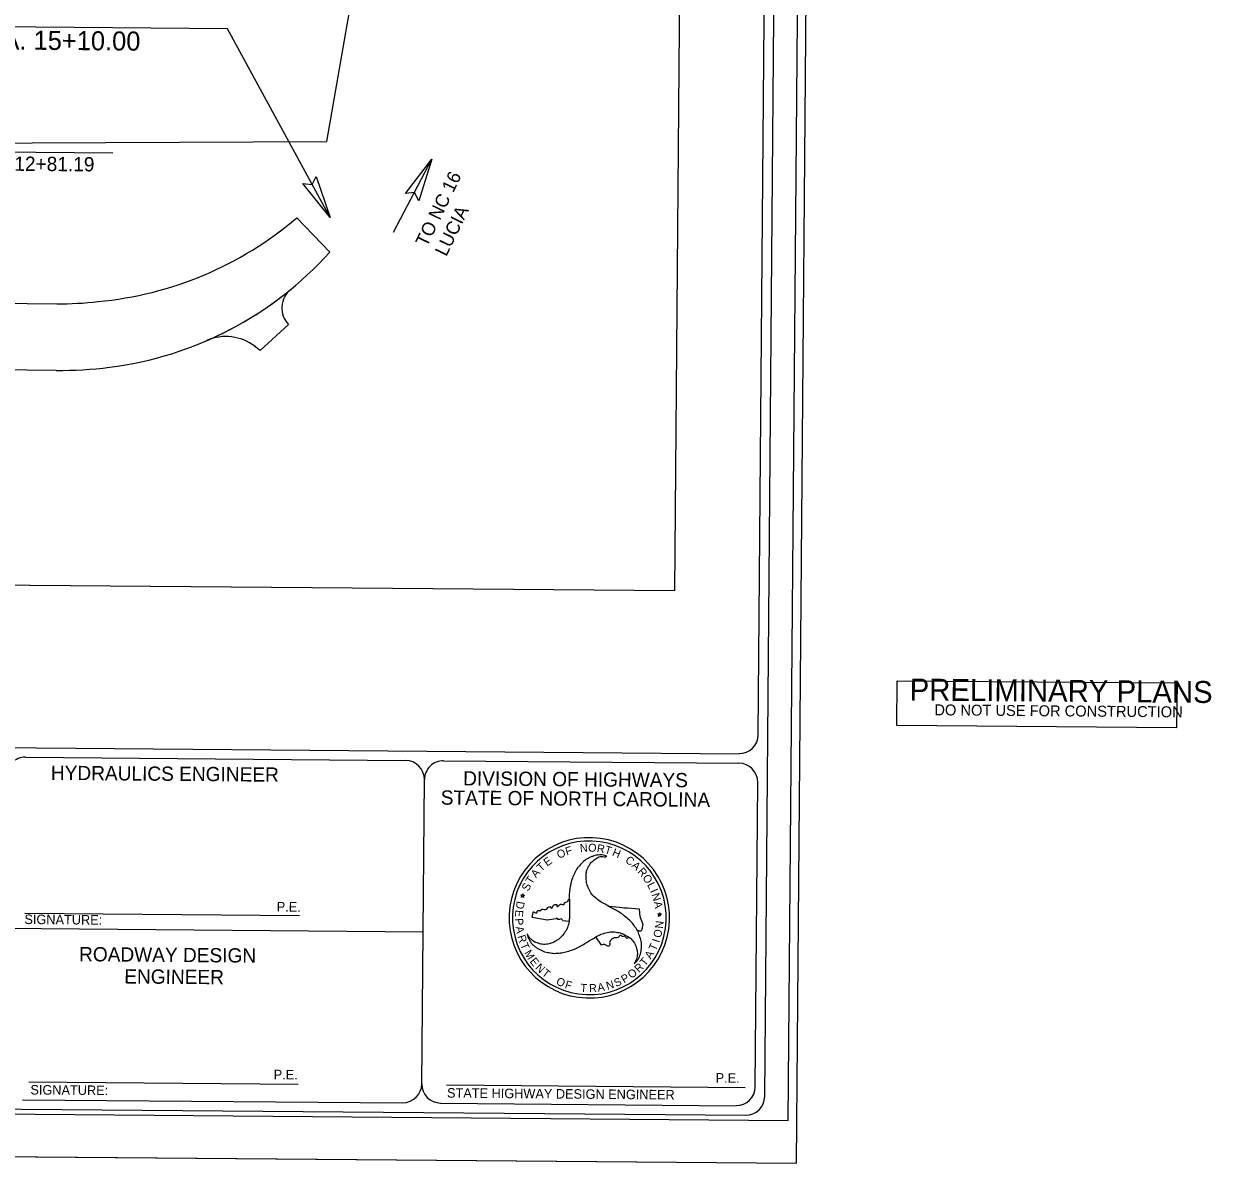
# Model space of a CAD drawing. Extents: x 1379453 to 1387082, y 594364 to 596664.
# Drawn here: x 1382008 to 1383256, y 594364 to 595562 of the extents above; entities that cross this region are included whole.
import ezdxf

# ---------------------------------------------------------------- set-up
doc = ezdxf.new("R2010")
doc.units = 0
for name, color, linetype in [('Old_Level_32', 7, 'Continuous'), ('Prop Horizontal Alignment Station Label', 7, 'Continuous'), ('Prop Shade Medium', 7, 'Continuous'), ('Prop Terminator CELL', 7, 'Continuous'), ('Sheet Clip Boundary CELL', 7, 'Continuous'), ('Sheet Cutting Line CELL', 7, 'Continuous'), ('Sheet Plot Border Inside CELL', 7, 'Continuous'), ('Sheet Plot Border Outside CELL', 7, 'Continuous'), ('Sheet Sticker Preliminary CELL', 7, 'Continuous'), ('Sheet Title CELL', 7, 'Continuous')]:
    doc.layers.add(name, color=color, linetype=linetype)

msp = doc.modelspace()

# ---------------------------------------------------------------- linework, layer by layer
at = {"layer": 'Old_Level_32'}
msp.add_lwpolyline([(1380751.9, 595954.7), (1382700.4, 595938.4), (1382692.2, 594965.7), (1380743.7, 594982)], close=True, dxfattribs=at)
at = {"layer": 'Prop Horizontal Alignment Station Label'}
for p, q in [((1382222.4, 595556.6), (1381829.5, 595559.9)), ((1382330.5, 595358.2), (1382222.4, 595556.6)), ((1381864.4, 595428.2), (1382101.9, 595426.2)), ((1382397, 595342.7), (1382437.3, 595419.6))]:
    msp.add_line(p, q, dxfattribs=at)
at = {"layer": 'Prop Shade Medium'}
for p, q in [((1382295.3, 595357.8), (1382329.9, 595321.7)), ((1381821.3, 595269.4), (1382043, 595267.5)), ((1382286.6, 595245.9), (1382256.7, 595218.5)), ((1382256.7, 595218.5), (1382251, 595222.9)), ((1382042.4, 595197.5), (1381820.7, 595199.4))]:
    msp.add_line(p, q, dxfattribs=at)
for centre, radius, start, end in [((1382052.1, 595643.3), 375, 275.2398, 310.4257), ((1382051.4, 595572.8), 375, 277.2254, 317.9654), ((1382051.4, 595572.8), 375, 293.4886, 309.2808), ((1382304.6, 595263.2), 25, 129.2808, 223.9334), ((1382046, 595617.5), 350, 269.52, 276.6264), ((1382220.8, 595183.1), 50, 52.7702, 113.4886), ((1382046, 595617.5), 420, 269.52, 277.1914)]:
    msp.add_arc(centre, radius, start, end, dxfattribs=at)
at = {"layer": 'Prop Terminator CELL'}
for points in [[(1382409.6, 595383.3), (1382437.3, 595419.6), (1382423.4, 595375.8), (1382419, 595384.6)], [(1382315.8, 595401.4), (1382330.5, 595358.2), (1382301.8, 595394.1), (1382311.6, 595392.8)]]:
    msp.add_lwpolyline(points, close=True, dxfattribs=at)
at = {"layer": 'Sheet Clip Boundary CELL'}
msp.add_lwpolyline([(1380751.9, 595954.7), (1381159.4, 595952.2), (1381397, 595433.8), (1382327, 595438.1), (1382414.4, 595940.9), (1382700.4, 595938.5), (1382692.2, 594965.7), (1380744.6, 594982)], close=True, dxfattribs=at)
at = {"layer": 'Sheet Cutting Line CELL'}
msp.add_line((1379452.6, 594392.2), (1382820.5, 594364), dxfattribs=at)
at = {"layer": 'Sheet Plot Border Inside CELL'}
msp.add_lwpolyline([(1379479, 594436.9), (1382811.8, 594409), (1382829.5, 596519.1), (1379496.6, 596547)], close=True, dxfattribs=at)
at = {"layer": 'Sheet Plot Border Outside CELL'}
msp.add_lwpolyline([(1382838.9, 596563.9), (1379471, 596592.1), (1379452.6, 594392.2), (1382820.5, 594364)], close=True, dxfattribs=at)
at = {"layer": 'Sheet Sticker Preliminary CELL'}
msp.add_lwpolyline([(1382926.1, 594824.3), (1382926.5, 594871.3), (1383220.5, 594868.9), (1383220.1, 594821.9)], close=True, dxfattribs=at)
at = {"layer": 'Sheet Title CELL'}
for p, q in [((1379920.2, 594818.3), (1382760.1, 594794.5)), ((1382010, 594790.8), (1382409.5, 594787.5)), ((1382449.5, 594787.1), (1382760, 594784.5)), ((1382426.7, 594447.3), (1382429.4, 594767.3)), ((1382621, 594686.9), (1382620.8, 594686.7)), ((1382621, 594686.9), (1382620.8, 594686.7)), ((1382531.8, 594645.1), (1382530.7, 594646.1)), ((1382530.7, 594646.1), (1382532.2, 594645.9)), ((1382531.2, 594643.8), (1382531.8, 594645.1)), ((1382532.4, 594644.5), (1382531.2, 594643.8)), ((1382532.2, 594645.9), (1382532.8, 594647.2)), ((1382533.5, 594643.4), (1382532.4, 594644.5)), ((1382532.8, 594647.2), (1382533.1, 594645.8)), ((1382533.1, 594645.8), (1382534.5, 594645.6)), ((1382534.5, 594645.6), (1382533.2, 594644.9)), ((1382533.2, 594644.9), (1382533.5, 594643.4)), ((1382622.6, 594634.3), (1382622.6, 594634.3)), ((1382009.6, 594626.8), (1382298.1, 594624.4)), ((1382542.8, 594622.5), (1382543.7, 594627.5)), ((1382558.6, 594619.6), (1382542.8, 594622.5)), ((1382568, 594621), (1382558.6, 594619.6)), ((1382581.4, 594618), (1382574.8, 594619)), ((1382676.1, 594626), (1382674.7, 594626.2)), ((1382674.7, 594626.2), (1382675.8, 594625.2)), ((1382675.8, 594625.2), (1382675.1, 594623.9)), ((1382675.1, 594623.9), (1382676.4, 594624.6)), ((1382676.8, 594627.3), (1382676.1, 594626)), ((1382676.4, 594624.6), (1382677.4, 594623.6)), ((1382677.1, 594625.9), (1382676.8, 594627.3)), ((1382678.5, 594625.7), (1382677.1, 594625.9)), ((1382677.2, 594625), (1382678.5, 594625.7)), ((1382677.4, 594623.6), (1382677.2, 594625)), ((1381986.7, 594611.1), (1382428, 594607.4)), ((1382686.3, 594610.2), (1382686.3, 594610.2)), ((1382615.6, 594593.4), (1382609.7, 594602)), ((1382609.7, 594602), (1382609.7, 594602)), ((1382013.7, 594449.7), (1382296.7, 594447.3)), ((1382452.6, 594446.4), (1382766.5, 594443.8))]:
    msp.add_line(p, q, dxfattribs=at)
for points in [[(1382787.1, 594434.3), (1382804.3, 596494.2)], [(1382780.2, 594814.3), (1382794.2, 596484.3)], [(1382777.1, 594444.4), (1382779.8, 594764.4)], [(1379807, 594439.2), (1382766.9, 594414.4)], [(1382007, 594430.8), (1382406.5, 594427.5)], [(1382446.5, 594427.1), (1382757, 594424.5)]]:
    msp.add_lwpolyline(points, dxfattribs=at)
for centre, radius, start, end in [((1382760.3, 594814.6), 20, 269.52, 359.52), ((1382009.9, 594770.9), 20, 89.52, 179.52), ((1382409.4, 594767.5), 20, 359.52, 89.52), ((1382449.4, 594767.1), 20, 89.52, 179.52), ((1382759.8, 594764.6), 20, 359.52, 89.52), ((1382602.8, 594622), 84.3, 351.9411, 171.9411), ((1382602.8, 594622), 80.8, 351.9411, 171.9411), ((1382676.4, 595075.8), 444.7, 257.6196, 257.7192), ((1382602.8, 594622), 84.3, 171.9411, 351.9411), ((1382602.8, 594622), 80.8, 171.9411, 351.9411), ((1382676.4, 595075.8), 444.7, 263.0587, 267.2647), ((1382406.7, 594447.6), 20, 269.52, 359.52), ((1382446.7, 594447.3), 20, 179.52, 269.52), ((1382757.2, 594444.6), 20, 269.52, 359.52), ((1382767.1, 594434.5), 20, 269.52, 359.52)]:
    msp.add_arc(centre, radius, start, end, dxfattribs=at)
for points in [[(1382620.8, 594686.7), (1382619, 594687.5), (1382613.4, 594688.1), (1382607.5, 594687.1), (1382607, 594686.9), (1382603.9, 594685.8), (1382600.6, 594684), (1382595.5, 594680.3), (1382591.3, 594675.5), (1382589.6, 594673.5), (1382588.2, 594670.9), (1382585.5, 594665.2), (1382583.7, 594659.7), (1382582.4, 594653.1), (1382581.7, 594647.2), (1382581.8, 594641.1), (1382582, 594634.9), (1382582, 594629), (1382582, 594622.9), (1382581.2, 594616.9), (1382581.1, 594616.4), (1382579.1, 594610.2), (1382575.7, 594605), (1382571.8, 594600.7), (1382569.5, 594598.9), (1382566.4, 594597.1), (1382564.6, 594596), (1382560.6, 594594.7), (1382554.7, 594594.1), (1382549.1, 594595.2), (1382544.3, 594597.2), (1382540.4, 594600.6), (1382537.5, 594605.1)], [(1382649.9, 594573.8), (1382651.4, 594575), (1382654.7, 594579.5), (1382656.8, 594585.1), (1382656.9, 594585.7), (1382657.4, 594588.9), (1382657.6, 594592.7), (1382657, 594598.9), (1382654.9, 594605), (1382654, 594607.5), (1382652.4, 594610.1), (1382648.9, 594615.2), (1382645, 594619.5), (1382639.9, 594623.9), (1382635.2, 594627.4), (1382629.8, 594630.4), (1382624.4, 594633.3), (1382619.3, 594636.3), (1382613.9, 594639.4), (1382609.2, 594643.1), (1382608.8, 594643.4), (1382604.4, 594648.3), (1382601.6, 594653.8), (1382599.9, 594659.3), (1382599.5, 594662.2), (1382599.5, 594665.8), (1382599.4, 594667.9), (1382600.3, 594672), (1382602.8, 594677.5), (1382606.5, 594681.7), (1382610.6, 594684.8), (1382615.5, 594686.5), (1382620.8, 594686.7), (1382621, 594686.9)], [(1382543.7, 594627.5), (1382543.6, 594628), (1382544.5, 594628.4), (1382546.7, 594627.1), (1382548, 594627.9), (1382548.1, 594629), (1382549.2, 594629.8), (1382550.8, 594629.3), (1382552.5, 594630.9), (1382553.9, 594631.1), (1382556.7, 594630.7), (1382560.5, 594633.6), (1382562, 594633.6), (1382562.2, 594632.6), (1382563, 594632.3), (1382564.9, 594634.9), (1382565.3, 594635.2), (1382568.1, 594635.9), (1382568.7, 594635.3), (1382568.7, 594634.1), (1382569, 594633.8), (1382570, 594634.2), (1382571.4, 594635.6), (1382573.7, 594636.4), (1382576.1, 594635.7), (1382576.8, 594637.7), (1382579.9, 594639.2), (1382580.7, 594640.3), (1382581, 594641.5)], [(1382581.8, 594641.3), (1382581.8, 594641.1), (1382582, 594634.9), (1382582, 594629), (1382582, 594622.9), (1382581.4, 594618)], [(1382653.5, 594608.5), (1382652.4, 594610.1), (1382648.9, 594615.2), (1382645, 594619.5), (1382639.9, 594623.9), (1382635.2, 594627.4), (1382629.8, 594630.4), (1382624.4, 594633.3), (1382622.6, 594634.3)], [(1382655.2, 594631.6), (1382655.6, 594625.8), (1382657.5, 594618.9), (1382658.9, 594615), (1382658.4, 594611.9), (1382657.2, 594608.3), (1382653.6, 594608.5)], [(1382574.8, 594619), (1382574.4, 594620.3), (1382573.1, 594620.8), (1382571.3, 594620.2), (1382570, 594620.4), (1382568.7, 594621.7), (1382568, 594621)], [(1382537.5, 594605.1), (1382537.8, 594603.1), (1382540.1, 594598), (1382543.9, 594593.4), (1382544.3, 594593.1), (1382546.8, 594590.9), (1382550.1, 594589), (1382555.8, 594586.3), (1382562, 594585.2), (1382564.6, 594584.7), (1382567.7, 594584.8), (1382573.8, 594585.3), (1382579.5, 594586.5), (1382585.9, 594588.7), (1382591.3, 594591), (1382596.6, 594594.1), (1382601.8, 594597.4), (1382607, 594600.4), (1382612.3, 594603.4), (1382617.9, 594605.7), (1382618.5, 594605.8), (1382624.8, 594607.3), (1382630.9, 594607), (1382636.5, 594605.7), (1382639.4, 594604.6), (1382642.4, 594602.8), (1382644.3, 594601.8), (1382647.4, 594599), (1382650.8, 594594.1), (1382652.6, 594588.8), (1382653.3, 594583.6), (1382652.3, 594578.5), (1382649.9, 594573.8)], [(1382609.7, 594602), (1382612.3, 594603.4), (1382617.9, 594605.7), (1382618.5, 594605.8), (1382624.8, 594607.3), (1382630.9, 594607), (1382636.5, 594605.7), (1382639.4, 594604.6), (1382642.4, 594602.8), (1382644.1, 594601.9)], [(1382644.1, 594601.8), (1382643.1, 594600.5), (1382641.9, 594600.6), (1382639.9, 594602.6), (1382637.1, 594602.5), (1382636, 594603.4), (1382635.2, 594603.5), (1382632.9, 594601.3), (1382630.1, 594601.1), (1382625.3, 594598.5), (1382624.2, 594596.8), (1382623.9, 594592.8), (1382622.8, 594592.1), (1382621.5, 594592.5), (1382619, 594593.9), (1382615.6, 594593.4)]]:
    msp.add_spline(points, degree=3, dxfattribs=at)

# ---------------------------------------------------------------- texts
at = {"layer": 'Prop Horizontal Alignment Station Label'}
for s, height, rotation, p in [('-L- POC STA. 15+10.00', 20, 359.52, (1381846.2, 595536)), ('-L- POT STA. 12+81.19', 15, 359.52, (1381871.3, 595408.4)), ('TO NC 16', 14, 64.1682, (1382432, 595326.4)), ('LUCIA', 14, 64.1682, (1382452.4, 595316.5))]:
    msp.add_text(s, height=height, rotation=rotation, dxfattribs=at).set_placement(p)
at = {"layer": 'Sheet Sticker Preliminary CELL'}
for s, height, p in [('PRELIMINARY PLANS', 23.04, (1382939.4, 594850.5)), ('DO NOT USE FOR CONSTRUCTION', 11.52, (1382965.4, 594834.9))]:
    msp.add_text(s, height=height, rotation=359.52, dxfattribs=at).set_placement(p)
at = {"layer": 'Sheet Title CELL'}
for s, height, rotation, p in [(' HYDRAULICS ENGINEER', 15, 359.52, (1382031.2, 594767.1)), ('DIVISION OF HIGHWAYS', 14.999, 359.52, (1382470.1, 594761.2)), ('STATE OF NORTH CAROLINA', 14.999, 359.52, (1382446.6, 594741)), ('O', 8.42, 24.1587, (1382570.8, 594683.9)), ('F', 8.43, 17.0119, (1382579, 594687.5)), ('N', 8.41, 4.9249, (1382593.2, 594691)), ('O', 8.43, 357.4268, (1382601.4, 594691.7)), ('R', 8.41, 350.8169, (1382610.3, 594691.3)), ('T', 8.43, 344.1673, (1382618.2, 594690)), ('H', 8.4, 337.0825, (1382626.1, 594687.7)), ('T', 8.39, 43.2137, (1382552.3, 594670.1)), ('E', 8.38, 36.0981, (1382558.4, 594675.7)), ('C', 8.39, 324.7402, (1382639.8, 594681)), ('A', 8.4, 317.2432, (1382646.6, 594676.2)), ('T', 8.43, 57.3212, (1382542.2, 594656.6)), ('A', 8.44, 50.2689, (1382546.8, 594663.4)), ('R', 8.4, 310.8792, (1382653, 594670.3)), ('O', 8.43, 303.7596, (1382658.2, 594664.2)), ('S', 8.4, 63.6974, (1382538.7, 594649.4)), ('L', 8.39, 297.5259, (1382663.2, 594656.8)), ('I', 8.42, 293.5366, (1382666.4, 594650.3)), ('N', 8.41, 287.8365, (1382668, 594646.5)), ('P.E.', 10, 359.52, (1382274.2, 594628.7)), ('E', 8.37, 266.082, (1382525.1, 594630.5)), ('D', 8.41, 259.7941, (1382526.7, 594640)), ('A', 8.41, 280.4045, (1382670.5, 594638.6)), ('SIGNATURE:', 10, 359.52, (1382009, 594615.5)), ('P', 8.41, 273.6144, (1382524.7, 594621.3)), ('N', 8.41, 84.1493, (1382680.1, 594610.4)), ('A', 8.4, 280.207, (1382525.2, 594612.4)), ('R', 8.41, 287.2756, (1382527.1, 594602.6)), ('O', 8.38, 76.9013, (1382677.9, 594600.4)), ('ROADWAY DESIGN', 14.999, 359.52, (1382066.4, 594576.4)), ('T', 8.4, 293.9262, (1382529.9, 594593.7)), ('T', 8.4, 66.1157, (1382672.4, 594586.6)), ('I', 8.43, 71.7656, (1382676.3, 594595.3)), ('M', 8.39, 301.1612, (1382533.9, 594585.1)), ('E', 8.39, 308.628, (1382539.6, 594576)), ('T', 8.38, 50.9443, (1382661.5, 594570.5)), ('A', 8.43, 59.0313, (1382667.4, 594578)), ('ENGINEER', 15, 359.52, (1382113.9, 594553)), ('N', 8.43, 315.5995, (1382545.4, 594569)), ('T', 8.4, 322.4415, (1382552.2, 594562.4)), ('O', 8.43, 37.6554, (1382647, 594557.6)), ('R', 8.42, 44.8445, (1382655, 594563.8)), ('O', 8.41, 335.7452, (1382567.1, 594552.4)), ('F', 8.4, 342.9104, (1382576.5, 594548.4)), ('A', 8.38, 9.5294, (1382612, 594544.4)), ('N', 8.38, 16.5611, (1382621.8, 594546.2)), ('S', 8.37, 23.7715, (1382630.8, 594549.1)), ('P', 8.41, 30.9634, (1382639.3, 594552.9)), ('T', 8.38, 355.8197, (1382593.2, 594544.4)), ('R', 8.42, 2.7763, (1382602.7, 594543.8)), ('P.E.', 10, 359.52, (1382271, 594452.3)), ('P.E.', 10, 359.52, (1382735.5, 594448.8)), ('SIGNATURE:', 10, 359.52, (1382015.3, 594436.3)), ('STATE HIGHWAY DESIGN ENGINEER', 10, 359.52, (1382453.2, 594433))]:
    msp.add_text(s, height=height, rotation=rotation, dxfattribs=at).set_placement(p)

doc.saveas('drawing.dxf')
